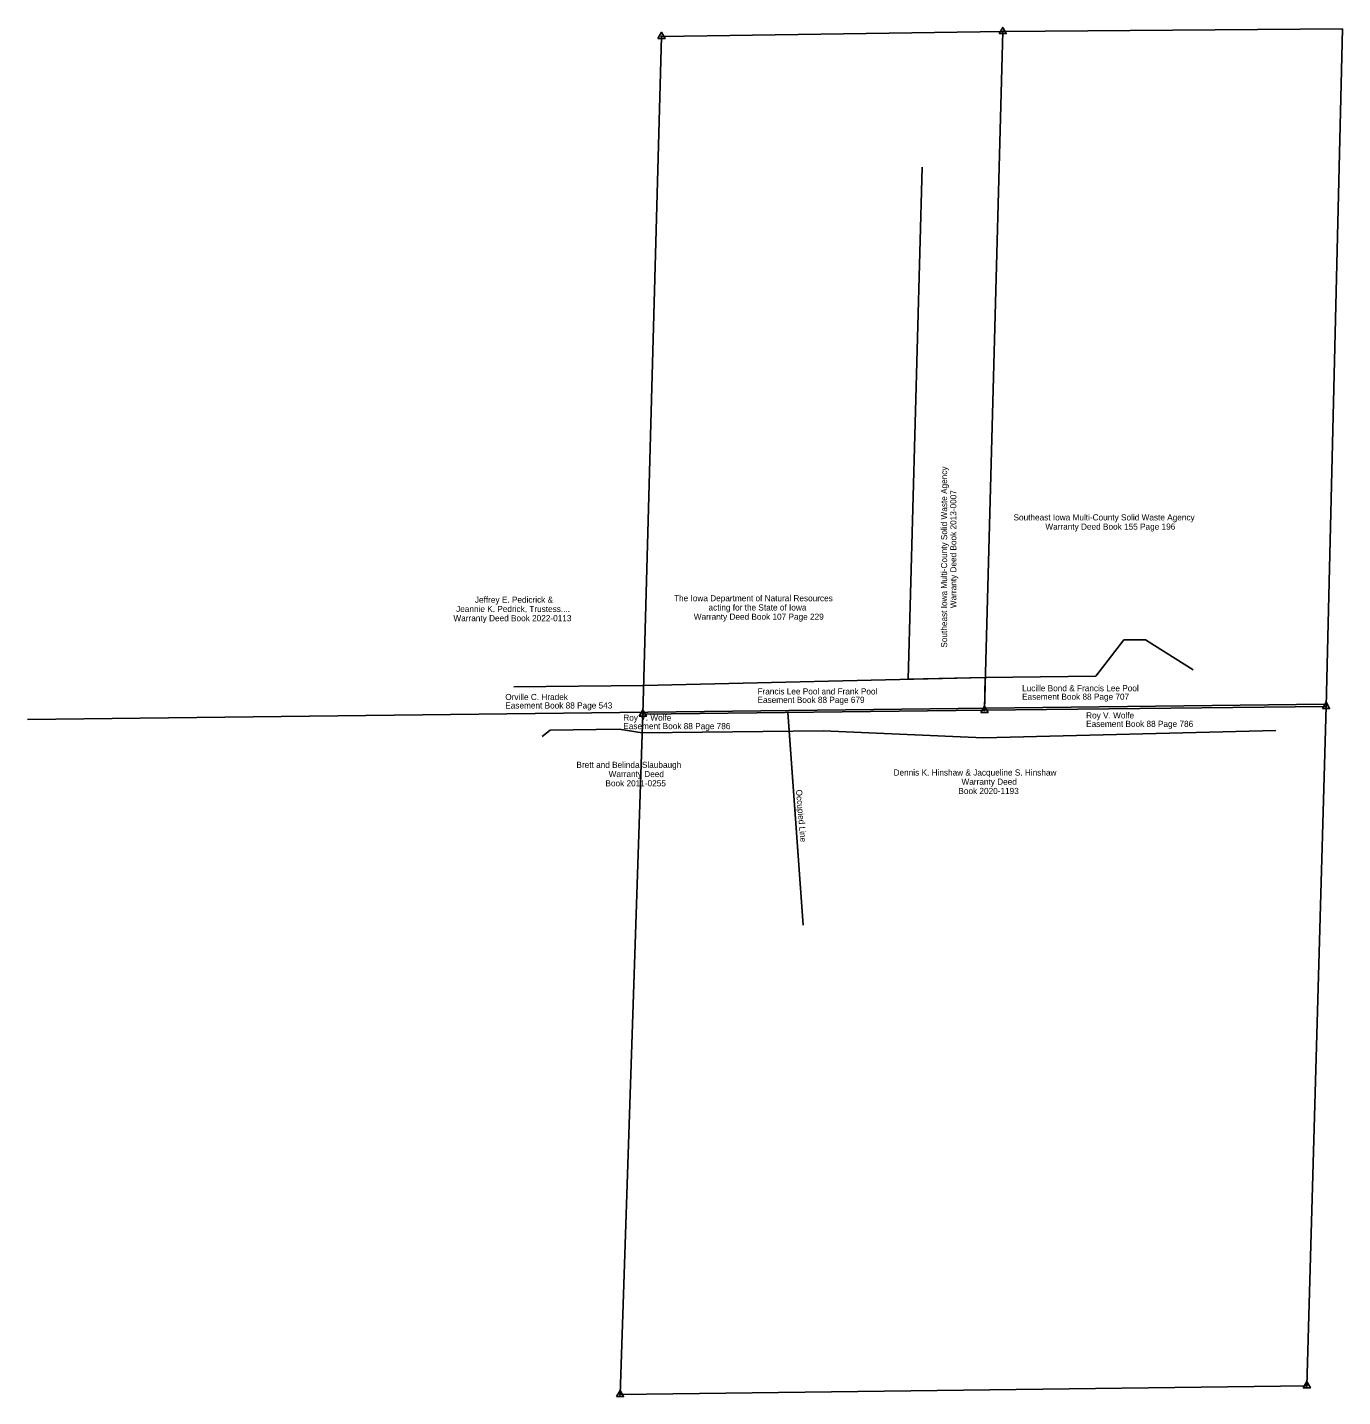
# Model space of a CAD drawing. Extents: x 23465703 to 23470832, y 6735468 to 6740807.
import ezdxf

# ---------------------------------------------------------------- set-up
doc = ezdxf.new("R2010")
doc.units = 0
for name, color, linetype in [('Alignment', 7, 'Continuous'), ('DisROW Existing', 7, 'Continuous'), ('DisROW Property Lines', 7, 'Continuous'), ('Fence', 7, 'Continuous'), ('ROWText', 7, 'Continuous'), ('Section Lines', 7, 'Continuous'), ('SurSectionCorner', 7, 'Continuous')]:
    doc.layers.add(name, color=color, linetype=linetype)

msp = doc.modelspace()

# ---------------------------------------------------------------- linework, layer by layer
at = {"layer": 'Alignment'}
msp.add_line((23465703.5, 6738107.4), (23470762.4, 6738167.1), dxfattribs=at)
msp.add_line((23465703.5, 6738107.4), (23470762.4, 6738167.1), dxfattribs=at)
at = {"layer": 'DisROW Existing'}
for p, q in [((23470832.3, 6740793.8), (23470832.3, 6740793.8)), ((23469870.2, 6738276.6), (23469978.6, 6738417.9)), ((23469978.6, 6738417.9), (23470063.6, 6738418.9)), ((23469978.6, 6738417.9), (23469978.6, 6738417.9)), ((23470063.6, 6738418.9), (23470063.6, 6738418.9)), ((23470063.6, 6738418.9), (23470250, 6738301.1)), ((23468106.4, 6738240.8), (23469438.9, 6738271.5)), ((23469438.9, 6738271.5), (23469870.2, 6738276.6)), ((23469438.9, 6738271.5), (23469438.9, 6738271.5)), ((23469870.2, 6738276.6), (23469870.2, 6738276.6)), ((23470250, 6738301.1), (23470250, 6738301.1)), ((23467600.6, 6738234.8), (23468106.4, 6738240.8)), ((23467600.6, 6738234.8), (23467600.6, 6738234.8)), ((23468106.4, 6738240.8), (23468106.4, 6738240.8)), ((23467710.9, 6738041.1), (23467742.6, 6738066.4)), ((23467710.9, 6738041.1), (23467710.9, 6738041.1)), ((23467742.6, 6738066.4), (23468010.6, 6738069.6)), ((23467742.6, 6738066.4), (23467742.6, 6738066.4)), ((23468010.6, 6738069.6), (23468010.6, 6738069.6)), ((23468010.6, 6738069.6), (23468100.9, 6738055.7)), ((23468100.9, 6738055.7), (23468806.7, 6738064)), ((23468100.9, 6738055.7), (23468100.9, 6738055.7)), ((23468806.7, 6738064), (23468806.7, 6738064)), ((23468806.7, 6738064), (23469432.4, 6738036.4)), ((23469432.4, 6738036.4), (23470571.3, 6738064.8)), ((23470571.3, 6738064.8), (23470571.3, 6738064.8)), ((23469432.4, 6738036.4), (23469432.4, 6738036.4))]:
    msp.add_line(p, q, dxfattribs=at)
at = {"layer": 'DisROW Property Lines'}
for p, q in [((23468103.4, 6738128.8), (23468176, 6740771.1)), ((23469192.4, 6740261.4), (23469138.6, 6738264.6)), ((23469138.6, 6738264.6), (23469438.9, 6738271.5)), ((23469438.9, 6738271.5), (23469435.5, 6738143.8)), ((23469435.5, 6738143.8), (23470767.6, 6738158.6)), ((23469435.5, 6738143.8), (23468103.4, 6738128.8)), ((23468729.3, 6737306.1), (23468668.4, 6738135.1))]:
    msp.add_line(p, q, dxfattribs=at)
at = {"layer": 'Fence'}
msp.add_line((23468729.3, 6737306.1), (23468672.3, 6738082.3), dxfattribs=at)
at = {"layer": 'Section Lines'}
for p, q in [((23468103.4, 6738128.8), (23468176, 6740771.1)), ((23468176, 6740771.1), (23469506.8, 6740790.2)), ((23469506.8, 6740790.2), (23469435.5, 6738143.8)), ((23470832.3, 6740800.3), (23469506.8, 6740790.2)), ((23470832.3, 6740800.3), (23470767.6, 6738158.6)), ((23470767.6, 6738158.6), (23469435.5, 6738143.8)), ((23470692.3, 6735510), (23470767.6, 6738158.6)), ((23468103.4, 6738128.8), (23468014.6, 6735475.6)), ((23469435.5, 6738143.8), (23468103.4, 6738128.8)), ((23468014.6, 6735475.6), (23470692.3, 6735510))]:
    msp.add_line(p, q, dxfattribs=at)
at = {"layer": 'SurSectionCorner'}
for points in [[(23468161.9, 6740763), (23468190.1, 6740763), (23468176, 6740787.4), (23468161.9, 6740763)], [(23469492.7, 6740782.1), (23469520.8, 6740782.1), (23469506.8, 6740806.5), (23469492.7, 6740782.1)], [(23469421.4, 6738135.6), (23469449.5, 6738135.6), (23469435.5, 6738160), (23469421.4, 6738135.6)], [(23470753.6, 6738150.5), (23470781.7, 6738150.5), (23470767.6, 6738174.9), (23470753.6, 6738150.5)], [(23468089.3, 6738120.6), (23468117.4, 6738120.6), (23468103.4, 6738145), (23468089.3, 6738120.6)], [(23468000.5, 6735467.5), (23468028.7, 6735467.5), (23468014.6, 6735491.9), (23468000.5, 6735467.5)], [(23470678.2, 6735501.8), (23470706.4, 6735501.8), (23470692.3, 6735526.2), (23470678.2, 6735501.8)]]:
    msp.add_lwpolyline(points, dxfattribs=at)
for centre in [(23468176, 6740771.1), (23469506.8, 6740790.2), (23470767.6, 6738158.6), (23468103.4, 6738128.8), (23469435.5, 6738143.8), (23468014.6, 6735475.6), (23470692.3, 6735510)]:
    msp.add_circle(centre, 1.61, dxfattribs=at)

# ---------------------------------------------------------------- texts
at = {"layer": 'DisROW Property Lines'}
for s, rotation, p in [('Southeast Iowa Multi-County Solid Waste Agency', 90, (23469290.1, 6738388)), ('Warranty Deed Book 2013-0007', 90, (23469326.1, 6738541.9)), ('Occupied Line', 275, (23468700.2, 6737833.2))]:
    msp.add_text(s, height=24, rotation=rotation, dxfattribs=at).set_placement(p)
for s, p in [('Southeast Iowa Multi-County Solid Waste Agency', (23469548.9, 6738884)), ('Warranty Deed Book 155 Page 196', (23469673.1, 6738848)), ('Jeffrey E. Pedicrick & ', (23467448.5, 6738562.9)), ('The Iowa Department of Natural Resources ', (23468225.2, 6738568.7)), ('Jeannie K. Pedrick, Trustess....', (23467375.4, 6738526.9)), ('Warranty Deed Book 107 Page 229', (23468302.2, 6738496.7)), ('acting for the State of Iowa', (23468359.6, 6738532.7)), ('Warranty Deed Book 2022-0113', (23467364.8, 6738490.9)), ('Brett and Belinda Slaubaugh', (23467844.6, 6737919.1)), ('Warranty Deed', (23467969.9, 6737883.1)), ('Dennis K. Hinshaw & Jacqueline S. Hinshaw', (23469081.3, 6737889.1)), ('Book 2011-0255', (23467957.8, 6737847.1)), ('Book 2020-1193', (23469333.9, 6737817.1)), ('Warranty Deed', (23469346.1, 6737853.1))]:
    msp.add_text(s, height=24, dxfattribs=at).set_placement(p)
at = {"layer": 'ROWText'}
for s, p in [('Orville C. Hradek', (23467567, 6738183.6)), ('Francis Lee Pool and Frank Pool', (23468550.6, 6738205.4)), ('Lucille Bond & Francis Lee Pool', (23469582.3, 6738217.8)), ('Easement Book 88 Page 707', (23469582.3, 6738184.8)), ('Easement Book 88 Page 543', (23467567, 6738150.6)), ('Easement Book 88 Page 679', (23468550.6, 6738172.4)), ('Roy V. Wolfe', (23468027.4, 6738103.1)), ('Easement Book 88 Page 786', (23468027.4, 6738070.1)), ('Roy V. Wolfe', (23469832.1, 6738111.8)), ('Easement Book 88 Page 786', (23469832.1, 6738078.8))]:
    msp.add_text(s, height=24, dxfattribs=at).set_placement(p)

doc.saveas('drawing.dxf')
